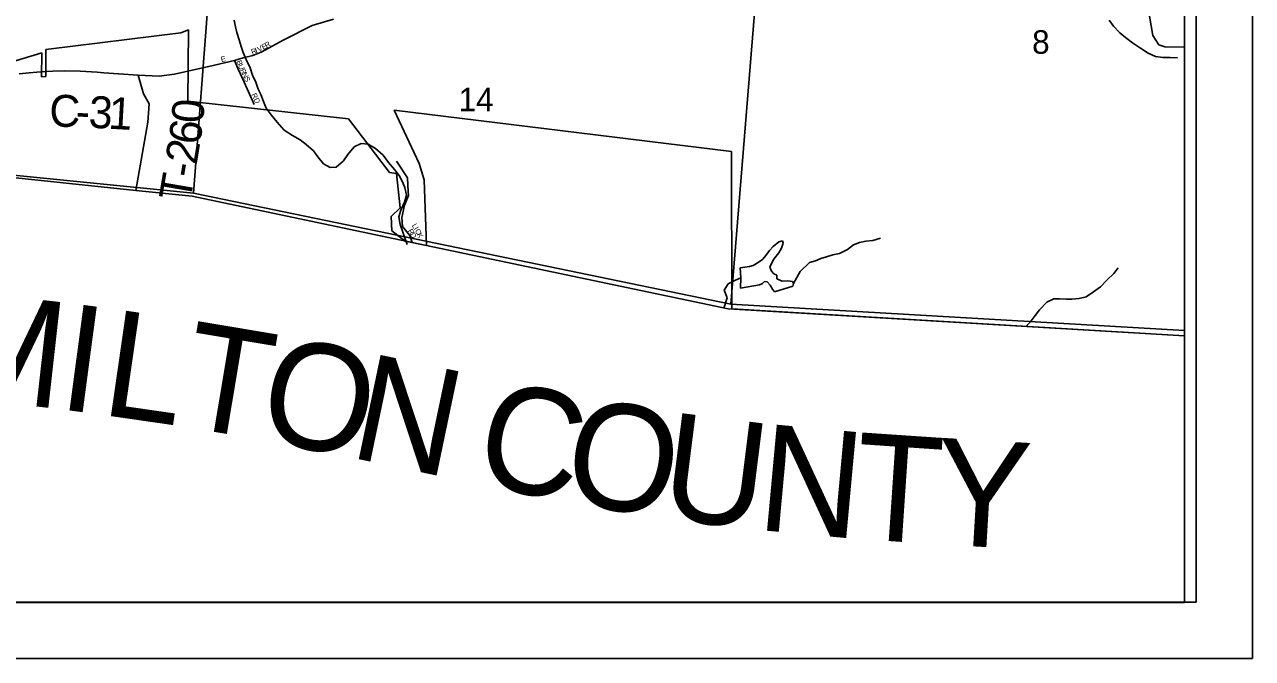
# Model space of a CAD drawing. Extents: x 0 to 34, y -2.3 to 22.
# Drawn here: x 6.815 to 9, y 14 to 15.127 of the extents above; entities that cross this region are included whole.
import ezdxf

# ---------------------------------------------------------------- set-up
doc = ezdxf.new("R2010")
doc.units = 0
for name, color, linetype in [('GM_X_Adjacent_County', 7, 'Continuous'), ('GM_X_Adjacent_County_Text', 7, 'Continuous'), ('GM_X_City_Street', 7, 'Continuous'), ('GM_X_City_Street_Text', 7, 'Continuous'), ('GM_X_Corporation', 7, 'Continuous'), ('GM_X_County', 7, 'Continuous'), ('GM_X_County_Road', 7, 'Continuous'), ('GM_X_County_Road_Text', 7, 'Continuous'), ('GM_X_Minor_River', 7, 'Continuous'), ('GM_X_Section', 7, 'Continuous'), ('GM_X_Section_Text', 7, 'Continuous'), ('GM_X_Township', 7, 'Continuous'), ('GM_X_Township_Road', 7, 'Continuous'), ('GM_X_Township_Road_Text', 7, 'Continuous'), ('SH_Data', 7, 'Continuous')]:
    doc.layers.add(name, color=color, linetype=linetype)

msp = doc.modelspace()

# ---------------------------------------------------------------- linework, layer by layer
at = {"layer": 'GM_X_Adjacent_County'}
for p, q in [((7.0132, 14.8324), (6.6675, 14.8683)), ((7.1135, 14.822), (7.0132, 14.8324)), ((7.5053, 14.7398), (7.1135, 14.822)), ((8.0675, 14.6219), (7.5053, 14.7398)), ((8.8792, 14.574), (8.0675, 14.6219)), ((8.8792, 14.0994), (8.8792, 14.574)), ((2.0792, 14.0994), (8.8792, 14.0994))]:
    msp.add_line(p, q, dxfattribs=at)
at = {"layer": 'GM_X_City_Street'}
for p, q in [((8.823, 15.1082), (8.796, 15.2645)), ((7.277, 15.1002), (7.3271, 15.1255)), ((7.3271, 15.1255), (7.3649, 15.137)), ((7.2366, 15.0781), (7.277, 15.1002)), ((8.8333, 15.0913), (8.823, 15.1082)), ((7.2216, 15.0721), (7.2366, 15.0781)), ((8.8442, 15.088), (8.8333, 15.0913)), ((8.8792, 15.0869), (8.8442, 15.088)), ((7.1433, 15.053), (7.1434, 15.053)), ((7.1434, 15.053), (7.1889, 15.0634)), ((7.1889, 15.0634), (7.2045, 15.068)), ((7.1954, 15.048), (7.1889, 15.0634)), ((7.2045, 15.068), (7.2216, 15.0721)), ((6.8452, 15.0434), (6.8521, 15.0439)), ((6.8521, 15.0439), (6.8553, 15.044)), ((7.2037, 15.0304), (7.1954, 15.048)), ((7.2241, 14.9852), (7.2037, 15.0304)), ((7.4913, 14.8064), (7.4985, 14.8233)), ((7.4982, 14.8296), (7.4982, 14.8298)), ((7.4985, 14.8233), (7.4982, 14.8296)), ((7.4865, 14.7844), (7.4913, 14.8064)), ((7.488, 14.768), (7.4865, 14.7844)), ((7.5006, 14.7522), (7.488, 14.768)), ((7.5053, 14.7398), (7.5006, 14.7522))]:
    msp.add_line(p, q, dxfattribs=at)
at = {"layer": 'GM_X_Corporation'}
for p, q in [((8.8792, 14.574), (8.8792, 17.9444)), ((7.0932, 15.1126), (7.1073, 15.1177)), ((7.1073, 15.1177), (7.1062, 14.9913)), ((6.8534, 15.0832), (7.0932, 15.1126)), ((6.6276, 15.0104), (6.8459, 15.0772)), ((6.8459, 15.0772), (6.8455, 15.0341)), ((6.8534, 15.0352), (6.8534, 15.0832)), ((6.8455, 15.0341), (6.8534, 15.0352)), ((7.1062, 14.9913), (7.3916, 14.9598)), ((7.5176, 14.8802), (7.473, 14.9754)), ((7.473, 14.9754), (8.0734, 14.9016)), ((7.3916, 14.9598), (7.4646, 14.8641)), ((8.0734, 14.9016), (8.0735, 14.6216)), ((7.5264, 14.8511), (7.5176, 14.8802)), ((7.4646, 14.8641), (7.4772, 14.8626)), ((7.4772, 14.8626), (7.4839, 14.8015)), ((7.5305, 14.7345), (7.5264, 14.8511)), ((7.4839, 14.8015), (7.4676, 14.7857)), ((7.4676, 14.7857), (7.469, 14.7604)), ((7.469, 14.7604), (7.4928, 14.7424)), ((7.4928, 14.7424), (7.5305, 14.7345)), ((8.0735, 14.6216), (8.8792, 14.574))]:
    msp.add_line(p, q, dxfattribs=at)
at = {"layer": 'GM_X_County'}
for p, q in [((8.8792, 14.574), (8.8792, 20.8994)), ((6.6675, 14.8683), (7.0132, 14.8324)), ((7.0132, 14.8324), (7.1135, 14.822)), ((7.1135, 14.822), (7.5053, 14.7398)), ((7.5053, 14.7398), (8.0675, 14.6219)), ((8.0675, 14.6219), (8.8792, 14.574))]:
    msp.add_line(p, q, dxfattribs=at)
at = {"layer": 'GM_X_County_Road'}
for p, q in [((7.124, 15.0485), (7.1433, 15.053)), ((6.8056, 15.0398), (6.8235, 15.0417)), ((6.8235, 15.0417), (6.8373, 15.0429)), ((6.8373, 15.0429), (6.8452, 15.0434)), ((6.8553, 15.044), (6.8659, 15.0444)), ((6.8659, 15.0444), (6.8872, 15.0453)), ((6.8872, 15.0453), (6.9144, 15.0444)), ((6.9144, 15.0444), (6.9447, 15.0425)), ((6.9447, 15.0425), (6.9567, 15.0417)), ((6.9567, 15.0417), (6.9827, 15.04)), ((6.9827, 15.04), (7.0174, 15.0371)), ((7.0174, 15.0371), (7.0549, 15.0357)), ((7.0549, 15.0357), (7.082, 15.0391)), ((7.082, 15.0391), (7.124, 15.0485))]:
    msp.add_line(p, q, dxfattribs=at)
at = {"layer": 'GM_X_Minor_River'}
for p, q in [((7.1885, 15.135), (7.1909, 15.1235)), ((7.1909, 15.1235), (7.1933, 15.1132)), ((8.7449, 15.1349), (8.7526, 15.1248)), ((8.7526, 15.1248), (8.7641, 15.1126)), ((7.1933, 15.1132), (7.1971, 15.1002)), ((7.1971, 15.1002), (7.2009, 15.0882)), ((8.7641, 15.1126), (8.7741, 15.1044)), ((8.7741, 15.1044), (8.7868, 15.0949)), ((7.2009, 15.0882), (7.2045, 15.0779)), ((7.2045, 15.0779), (7.2098, 15.0655)), ((8.7868, 15.0949), (8.8006, 15.0854)), ((8.8006, 15.0854), (8.8144, 15.0763)), ((8.8144, 15.0763), (8.8276, 15.0706)), ((7.2098, 15.0655), (7.2166, 15.0505)), ((8.8276, 15.0706), (8.8408, 15.0687)), ((8.8408, 15.0687), (8.8537, 15.0687)), ((8.8537, 15.0687), (8.8667, 15.0684)), ((7.2166, 15.0505), (7.2212, 15.0371)), ((7.2212, 15.0371), (7.227, 15.0247)), ((7.227, 15.0247), (7.2312, 15.0124)), ((7.2312, 15.0124), (7.2359, 15.0028)), ((7.2359, 15.0028), (7.2408, 14.9905)), ((7.2408, 14.9905), (7.2455, 14.9786)), ((7.2455, 14.9786), (7.2543, 14.9669)), ((7.2543, 14.9669), (7.2646, 14.9537)), ((7.2646, 14.9537), (7.2771, 14.9396)), ((7.2771, 14.9396), (7.292, 14.9301)), ((7.292, 14.9301), (7.3055, 14.9221)), ((7.3055, 14.9221), (7.3167, 14.9142)), ((7.3167, 14.9142), (7.3293, 14.9025)), ((7.3293, 14.9025), (7.337, 14.8924)), ((7.3907, 14.8962), (7.4017, 14.9096)), ((7.4017, 14.9096), (7.4144, 14.9158)), ((7.4144, 14.9158), (7.4265, 14.9147)), ((7.4265, 14.9147), (7.4396, 14.9071)), ((7.4396, 14.9071), (7.4534, 14.8949)), ((7.337, 14.8924), (7.3473, 14.8799)), ((7.3473, 14.8799), (7.3593, 14.8731)), ((7.3696, 14.8736), (7.3828, 14.885)), ((7.3828, 14.885), (7.3907, 14.8962)), ((7.4534, 14.8949), (7.4629, 14.8821)), ((7.4629, 14.8821), (7.4736, 14.8696)), ((7.3593, 14.8731), (7.3696, 14.8736)), ((7.4736, 14.8696), (7.482, 14.8591)), ((7.482, 14.8591), (7.4875, 14.8491)), ((7.4875, 14.8491), (7.4917, 14.8375)), ((7.4917, 14.8375), (7.4948, 14.8238)), ((7.4948, 14.8238), (7.4914, 14.8113)), ((7.4849, 14.7974), (7.4816, 14.7853)), ((7.4914, 14.8113), (7.4849, 14.7974)), ((7.4816, 14.7853), (7.4835, 14.7719)), ((7.4835, 14.7719), (7.4961, 14.7362)), ((8.3249, 14.7435), (8.338, 14.7477)), ((8.1405, 14.7253), (8.1342, 14.7167)), ((8.1475, 14.7327), (8.1405, 14.7253)), ((8.1576, 14.7412), (8.1475, 14.7327)), ((8.1571, 14.7214), (8.1619, 14.7296)), ((8.1642, 14.7429), (8.1576, 14.7412)), ((8.1619, 14.7296), (8.1648, 14.7383)), ((8.1648, 14.7383), (8.1642, 14.7429)), ((8.2654, 14.72), (8.2793, 14.7272)), ((8.2793, 14.7272), (8.2905, 14.7357)), ((8.2905, 14.7357), (8.3009, 14.74)), ((8.3009, 14.74), (8.312, 14.7423)), ((8.312, 14.7423), (8.3249, 14.7435)), ((8.1225, 14.7052), (8.1116, 14.699)), ((8.129, 14.71), (8.1225, 14.7052)), ((8.1342, 14.7167), (8.129, 14.71)), ((8.1416, 14.6959), (8.1477, 14.7095)), ((8.1477, 14.7095), (8.1571, 14.7214)), ((8.1954, 14.6884), (8.2117, 14.7043)), ((8.2117, 14.7043), (8.2225, 14.7074)), ((8.2225, 14.7074), (8.2321, 14.711)), ((8.2321, 14.711), (8.2424, 14.7141)), ((8.2424, 14.7141), (8.2535, 14.7176)), ((8.2535, 14.7176), (8.2654, 14.72)), ((8.1051, 14.6969), (8.0887, 14.6947)), ((8.0887, 14.6947), (8.0898, 14.6771)), ((8.1116, 14.699), (8.1051, 14.6969)), ((8.1444, 14.6886), (8.1416, 14.6959)), ((8.1485, 14.6843), (8.1444, 14.6886)), ((8.1537, 14.6819), (8.1485, 14.6843)), ((8.1539, 14.675), (8.1537, 14.6819)), ((8.1837, 14.6666), (8.1954, 14.6884)), ((8.7407, 14.6725), (8.7532, 14.6844)), ((8.7532, 14.6844), (8.7614, 14.6948)), ((8.067, 14.6663), (8.0599, 14.6547)), ((8.0801, 14.6725), (8.067, 14.6663)), ((8.0898, 14.6771), (8.0801, 14.6725)), ((8.0898, 14.6771), (8.0893, 14.6585)), ((8.0893, 14.6585), (8.1229, 14.6644)), ((8.1229, 14.6644), (8.1283, 14.667)), ((8.1283, 14.667), (8.1318, 14.6703)), ((8.1318, 14.6703), (8.1367, 14.6698)), ((8.1367, 14.6698), (8.1418, 14.6636)), ((8.1418, 14.6636), (8.1462, 14.6566)), ((8.1495, 14.6519), (8.1825, 14.6621)), ((8.1633, 14.671), (8.1539, 14.675)), ((8.1732, 14.6715), (8.1633, 14.671)), ((8.1819, 14.6701), (8.1732, 14.6715)), ((8.1837, 14.6666), (8.1819, 14.6701)), ((8.1825, 14.6621), (8.1837, 14.6666)), ((8.7173, 14.6518), (8.7294, 14.661)), ((8.7294, 14.661), (8.7407, 14.6725)), ((8.0652, 14.6416), (8.0594, 14.623)), ((8.0599, 14.6547), (8.0652, 14.6416)), ((8.1462, 14.6566), (8.1495, 14.6519)), ((8.634, 14.6339), (8.6467, 14.6393)), ((8.6467, 14.6393), (8.657, 14.6398)), ((8.657, 14.6398), (8.6691, 14.639)), ((8.6691, 14.639), (8.6786, 14.6388)), ((8.6786, 14.6388), (8.6915, 14.64)), ((8.6915, 14.64), (8.7042, 14.6434)), ((8.7042, 14.6434), (8.7173, 14.6518)), ((8.6132, 14.6101), (8.6211, 14.6202)), ((8.6211, 14.6202), (8.634, 14.6339)), ((8.5976, 14.5909), (8.6045, 14.5982)), ((8.6045, 14.5982), (8.6132, 14.6101))]:
    msp.add_line(p, q, dxfattribs=at)
at = {"layer": 'GM_X_Section'}
for p, q in [((8.1532, 15.6343), (8.0719, 14.63)), ((8.1532, 15.6343), (8.0719, 14.63)), ((8.8792, 14.583), (8.8792, 15.6103)), ((7.1158, 14.8273), (7.1598, 15.3938)), ((7.1598, 15.3938), (7.1158, 14.8273)), ((7.1158, 14.8273), (6.3589, 14.9031)), ((8.0719, 14.63), (7.1158, 14.8273)), ((8.0719, 14.63), (8.8792, 14.583))]:
    msp.add_line(p, q, dxfattribs=at)
at = {"layer": 'GM_X_Township'}
for p, q in [((8.8792, 14.574), (8.8792, 17.9482)), ((6.6675, 14.8683), (7.0132, 14.8324)), ((7.0132, 14.8324), (7.1135, 14.822)), ((7.1135, 14.822), (7.5053, 14.7398)), ((7.5053, 14.7398), (8.0675, 14.6219)), ((8.0675, 14.6219), (8.8792, 14.574))]:
    msp.add_line(p, q, dxfattribs=at)
at = {"layer": 'GM_X_Township_Road'}
for p, q in [((7.0174, 15.0371), (7.0268, 15.004)), ((7.0268, 15.004), (7.0369, 14.9866)), ((7.0369, 14.9866), (7.0349, 14.9535)), ((7.0349, 14.9535), (7.0132, 14.8324)), ((7.497, 14.8545), (7.4769, 14.8843)), ((7.4982, 14.8298), (7.497, 14.8545))]:
    msp.add_line(p, q, dxfattribs=at)
at = {"layer": 'SH_Data'}
for p, q in [((9, 21), (9, 14)), ((8.9, 20.9), (8.9, 14.1)), ((2.1, 14.1), (8.9, 14.1)), ((2, 14), (9, 14))]:
    msp.add_line(p, q, dxfattribs=at)

# ---------------------------------------------------------------- texts
at = {"layer": 'GM_X_Adjacent_County_Text'}
for s, rotation, p in [('M', 353.5987, (6.6687, 14.4669)), ('I', 352.3925, (6.8722, 14.4441)), ('L', 351.7859, (6.9485, 14.4339)), ('T', 350.5023, (7.0876, 14.4139)), ('O', 348.8824, (7.2259, 14.3907)), ('N', 348.1806, (7.3897, 14.3586)), ('C', 348.4622, (7.6109, 14.3122)), ('O', 350.2942, (7.7685, 14.2802)), ('U', 352.8399, (7.9427, 14.2506)), ('N', 354.7403, (8.1157, 14.229)), ('T', 356.1448, (8.2875, 14.2132)), ('Y', 356.6389, (8.4307, 14.2036))]:
    msp.add_text(s, height=0.1894, rotation=rotation, dxfattribs=at).set_placement(p)
at = {"layer": 'GM_X_City_Street_Text'}
for s, rotation, p in [('R', 29.4805, (7.2461, 15.0854)), ('R', 21.4045, (7.2207, 15.0737)), ('I', 21.4043, (7.2276, 15.0764)), ('V', 25.7912, (7.2322, 15.0782)), ('E', 29.4039, (7.2403, 15.0822)), ('E', 14.0411, (7.1659, 15.0604)), ('B', 290.6897, (7.1921, 15.0618)), ('U', 292.3916, (7.1949, 15.0545)), ('R', 296.1662, (7.1984, 15.0462)), ('N', 296.5674, (7.2017, 15.0394)), ('S', 296.5651, (7.2054, 15.0319)), ('RD', 295.2019, (7.2187, 15.0028)), ('L', 301.0165, (7.504, 14.77)), ('I', 301.0162, (7.5074, 14.7643)), ('R', 303.5991, (7.4966, 14.7602)), ('D', 299.1905, (7.5007, 14.7541)), ('C', 298.7486, (7.5095, 14.7608)), ('K', 296.5651, (7.5131, 14.7543))]:
    msp.add_text(s, height=0.00947, rotation=rotation, dxfattribs=at).set_placement(p)
at = {"layer": 'GM_X_County_Road_Text'}
for s, rotation, p in [('C', 359.1901, (6.8593, 14.9458)), ('3', 356.9386, (6.9286, 14.9441)), ('1', 356.8187, (6.9635, 14.9422)), ('-', 357.3411, (6.9054, 14.9452))]:
    msp.add_text(s, height=0.0568, rotation=rotation, dxfattribs=at).set_placement(p)
at = {"layer": 'GM_X_Section_Text'}
for s, height, p in [('8', 0.0419, (8.608, 15.0754)), ('14', 0.04186, (7.5876, 14.9732))]:
    msp.add_text(s, height=height, rotation=0, dxfattribs=at).set_placement(p)
at = {"layer": 'GM_X_Township_Road_Text'}
for s, rotation, p in [('0', 85.2694, (7.1329, 14.9505)), ('6', 81.438, (7.1272, 14.9118)), ('2', 80.5821, (7.1214, 14.8764)), ('-', 80.3044, (7.1174, 14.8531)), ('T', 80.2372, (7.1102, 14.8111))]:
    msp.add_text(s, height=0.0568, rotation=rotation, dxfattribs=at).set_placement(p)

doc.saveas('drawing.dxf')
